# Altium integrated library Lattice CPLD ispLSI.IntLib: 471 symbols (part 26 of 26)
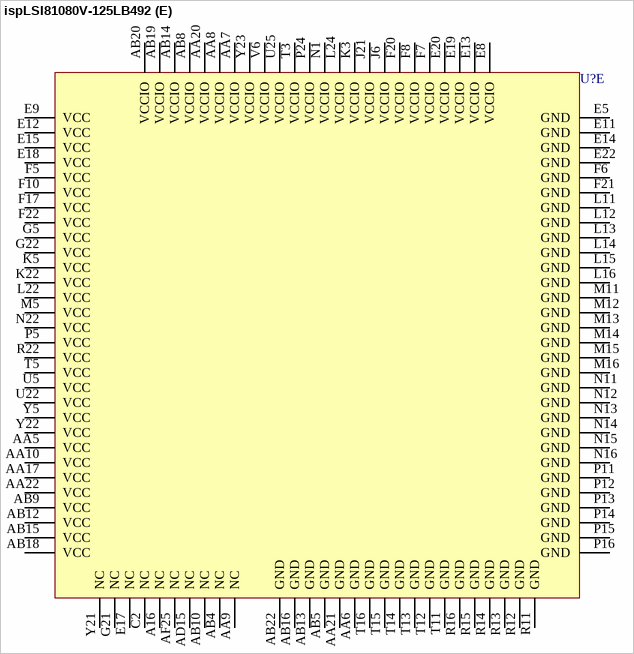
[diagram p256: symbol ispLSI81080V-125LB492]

## ispLSI81080V-125LB492
designator U?
3.3V In-System Programmable SuperBIG High Density PLD
footprint BGA492 (BGA, 492-Leads, Body 35x35mm, Pitch 1.27mm)
3D model 81080V-BGA492 (492-Ball Ball Grid Array (BGA492))
part A pins: A1 I/OB0 <13> (io), A2 TCK (in), A3 I/OB1 <23> (io), A4 I/OB1 <20> (io), A5 I/OB1 <16> (io), A6 I/OB2 <23> (io), A7 I/OB2 <19> (io), A8 I/OB2 <15> (io), A15 QIOCLK2 (in), AB1 I/OB0 <1> (io), AB2 I/OB0 <2> (io), AB3 I/OB0 <3> (io), AB6 I/OB0 <11> (io), AB7 I/OB1 <10> (io), AB17 CLKEN (in), AC1 I/OB0 <4> (io), AC2 I/OB0 <5> (io), AC3 I/OB0 <6> (io), AC4 TMS (in), AC5 I/OB1 <7> (io), AC6 I/OB2 <0> (io), AC7 I/OB2 <4> (io), AC8 I/OB2 <8> (io), AC15 CLK0 (in), AD1 I/OB0 <7> (io), AD2 I/OB0 <8> (io), AD3 I/OB0 <9> (io), AD4 I/OB1 <4> (io), AD5 I/OB1 <8> (io), AD6 I/OB2 <1> (io), AD7 I/OB2 <5> (io), AD8 I/OB2 <9> (io), AE1 I/OB0 <10> (io), AE2 I/OB1 <0> (io), AE3 I/OB1 <2> (io), AE4 I/OB1 <5> (io), AE5 I/OB1 <9> (io), AE6 I/OB2 <2> (io), AE7 I/OB2 <6> (io), AE8 I/OB2 <10> (io), AE14 QIOCLK0 (in), AF1 TDI (in), AF2 I/OB1 <1> (io), AF3 I/OB1 <3> (io), AF4 I/OB1 <6> (io), AF5 I/OB1 <11> (io), AF6 I/OB2 <3> (io), AF7 I/OB2 <7> (io), AF8 I/OB2 <11> (io), AF15 GOE0 (in), B1 I/OB0 <19> (io), B2 I/OB0 <18> (io), B3 TDO (out), B4 I/OB1 <21> (io), B5 I/OB1 <17> (io), B6 I/OB1 <12> (io), B7 I/OB2 <20> (io), B8 I/OB2 <16> (io), B9 I/OB2 <12> (io), B15 CLK2 (in), B26 EPEN (in), C1 I/OB0 <21> (io), C3 I/OB0 <14> (io), C4 I/OB1 <22> (io), C5 I/OB1 <18> (io), C6 I/OB1 <14> (io), C7 I/OB2 <21> (io), C8 I/OB2 <17> (io), C9 I/OB2 <13> (io), D1 I/OB0 <23> (io), D2 I/OB0 <22> (io), D3 I/OB0 <20> (io), D4 I/OB0 <15> (io), D5 I/OB1 <19> (io), D6 I/OB1 <15> (io), D7 I/OB2 <22> (io), D8 I/OB2 <18> (io), D9 I/OB2 <14> (io), D16 GOE2 (in), E6 I/OB0 <12> (io), E7 I/OB1 <13> (io), E16 IOCLKEN (in), F9 I/OB0 <17> (io), G6 I/OB0 <16> (io), L5 TOE (in), N3 QIOCLK3 (in), N5 GOE3 (in), P2 SET/RESET (in), P22 QIOCLK1 (in), P23 GOE1 (in), R24 CLK1 (in), Y6 I/OB0 <0> (io)
part B pins: A9 I/OB3 <23> (io), A10 I/OB3 <19> (io), A11 I/OB3 <15> (io), A12 I/OB3 <12> (io), A13 I/OB4 <20> (io), A14 I/OB4 <15> (io), A17 I/OB5 <21> (io), A18 I/OB5 <17> (io), A19 I/OB5 <13> (io), A20 I/OB6 <20> (io), A21 I/OB6 <16> (io), A22 I/OB6 <12> (io), AA19 I/OB6 <3> (io), AB11 I/OB3 <10> (io), AC9 I/OB3 <0> (io), AC10 I/OB3 <4> (io), AC11 I/OB3 <11> (io), AC12 I/OB4 <4> (io), AC13 I/OB4 <8> (io), AC14 I/OB4 <9> (io), AC16 I/OB5 <2> (io), AC17 I/OB5 <8> (io), AC18 I/OB6 <0> (io), AC19 I/OB6 <5> (io), AC20 I/OB6 <9> (io), AD9 I/OB3 <1> (io), AD10 I/OB3 <5> (io), AD11 I/OB3 <9> (io), AD12 I/OB4 <3> (io), AD13 I/OB4 <7> (io), AD14 I/OB4 <10> (io), AD16 I/OB5 <3> (io), AD17 I/OB5 <7> (io), AD18 I/OB5 <11> (io), AD19 I/OB6 <4> (io), AD20 I/OB6 <8> (io), AE9 I/OB3 <2> (io), AE10 I/OB3 <6> (io), AE11 I/OB3 <8> (io), AE12 I/OB4 <1> (io), AE13 I/OB4 <5> (io), AE15 I/OB5 <0> (io), AE16 I/OB5 <4> (io), AE17 I/OB5 <6> (io), AE18 I/OB5 <10> (io), AE19 I/OB6 <2> (io), AE20 I/OB6 <7> (io), AE21 I/OB6 <11> (io), AF9 I/OB3 <3> (io), AF10 I/OB3 <7> (io), AF11 I/OB4 <0> (io), AF12 I/OB4 <2> (io), AF13 I/OB4 <6> (io), AF14 I/OB4 <11> (io), AF16 I/OB5 <1> (io), AF17 I/OB5 <5> (io), AF18 I/OB5 <9> (io), AF19 I/OB6 <1> (io), AF20 I/OB6 <6> (io), AF21 I/OB6 <10> (io), B10 I/OB3 <20> (io), B11 I/OB3 <18> (io), B12 I/OB3 <14> (io), B13 I/OB4 <21> (io), B14 I/OB4 <14> (io), B16 I/OB5 <22> (io), B17 I/OB5 <20> (io), B18 I/OB5 <16> (io), B19 I/OB5 <12> (io), B20 I/OB6 <19> (io), B21 I/OB6 <15> (io), C10 I/OB3 <21> (io), C11 I/OB3 <17> (io), C12 I/OB4 <23> (io), C13 I/OB4 <19> (io), C14 I/OB4 <16> (io), C15 I/OB4 <12> (io), C16 I/OB5 <23> (io), C17 I/OB5 <19> (io), C18 I/OB5 <15> (io), C19 I/OB6 <23> (io), C20 I/OB6 <18> (io), C21 I/OB6 <14> (io), D10 I/OB3 <22> (io), D11 I/OB3 <16> (io), D12 I/OB4 <22> (io), D13 I/OB4 <18> (io), D14 I/OB4 <17> (io), D15 I/OB4 <13> (io), D17 I/OB5 <18> (io), D18 I/OB5 <14> (io), D19 I/OB6 <22> (io), D20 I/OB6 <17> (io), D21 I/OB6 <13> (io), E10 I/OB3 <13> (io), F19 I/OB6 <21> (io)
part C pins: A23 I/OB7 <20> (io), A24 I/OB7 <17> (io), A25 I/OB7 <15> (io), A26 I/OB7 <12> (io), AA1 I/OG0 <3> (io), AA2 I/OG0 <2> (io), AA3 I/OG0 <1> (io), AA4 I/OG0 <0> (io), AA18 I/OB8 <11> (io), AA23 I/OG0 <20> (io), AA24 I/OG0 <19> (io), AA25 I/OG0 <18> (io), AA26 I/OG0 <17> (io), AB21 I/OB8 <0> (io), AB23 I/OB8 <8> (io), AB24 I/OG0 <23> (io), AB25 I/OG0 <22> (io), AB26 I/OG0 <21> (io), AC21 I/OB7 <1> (io), AC22 I/OB7 <5> (io), AC23 I/OB8 <3> (io), AC24 I/OB8 <6> (io), AC25 I/OB8 <9> (io), AC26 I/OB8 <10> (io), AD21 I/OB7 <0> (io), AD22 I/OB7 <4> (io), AD23 I/OB7 <8> (io), AD24 I/OB7 <11> (io), AD25 I/OB8 <5> (io), AD26 I/OB8 <7> (io), AE22 I/OB7 <3> (io), AE23 I/OB7 <7> (io), AE24 I/OB7 <10> (io), AE25 I/OB8 <2> (io), AE26 I/OB8 <4> (io), AF22 I/OB7 <2> (io), AF23 I/OB7 <6> (io), AF24 I/OB7 <9> (io), AF26 I/OB8 <1> (io), B22 I/OB7 <23> (io), B23 I/OB7 <19> (io), B24 I/OB7 <16> (io), B25 I/OB7 <14> (io), C22 I/OB7 <22> (io), C23 I/OB7 <18> (io), C24 I/OB8 <21> (io), C25 I/OB8 <20> (io), C26 I/OB8 <19> (io), D22 I/OB7 <21> (io), D23 I/OB7 <13> (io), D24 I/OB8 <18> (io), D25 I/OB8 <17> (io), D26 I/OB8 <16> (io), E21 I/OB8 <22> (io), E23 I/OB8 <15> (io), E24 I/OB8 <14> (io), E25 I/OB8 <13> (io), E26 I/OB8 <12> (io), F18 I/OB8 <23> (io), T2 I/OG1 <0> (io), U1 I/OG1 <2> (io), U2 I/OG1 <3> (io), U3 I/OG1 <4> (io), U4 I/OG1 <5> (io), U6 I/OG0 <11> (io), U21 I/OG0 <12> (io), U23 I/OG1 <22> (io), U24 I/OG1 <23> (io), V1 I/OG1 <6> (io), V2 I/OG1 <8> (io), V3 I/OG1 <9> (io), V4 I/OG1 <10> (io), V5 I/OG1 <7> (io), V21 I/OG0 <16> (io), V22 I/OG1 <16> (io), V23 I/OG1 <17> (io), V24 I/OG1 <18> (io), V25 I/OG1 <19> (io), V26 I/OG1 <20> (io), W1 I/OG1 <11> (io), W2 I/OG0 <10> (io), W3 I/OG0 <9> (io), W4 I/OG0 <8> (io), W5 I/OG1 <1> (io), W22 I/OG1 <21> (io), W23 I/OG1 <12> (io), W24 I/OG1 <13> (io), W25 I/OG1 <14> (io), W26 I/OG1 <15> (io), Y1 I/OG0 <7> (io), Y2 I/OG0 <6> (io), Y3 I/OG0 <5> (io), Y4 I/OG0 <4> (io), Y24 I/OG0 <15> (io), Y25 I/OG0 <14> (io), Y26 I/OG0 <13> (io)
part D pins: E1 I/OG5 <3> (io), E2 I/OG5 <2> (io), E3 I/OG5 <1> (io), E4 I/OG5 <0> (io), F1 I/OG5 <7> (io), F2 I/OG5 <6> (io), F3 I/OG5 <5> (io), F4 I/OG5 <4> (io), F23 I/OG5 <23> (io), F24 I/OG5 <22> (io), F25 I/OG5 <21> (io), F26 I/OG5 <20> (io), G1 I/OG5 <11> (io), G2 I/OG5 <10> (io), G3 I/OG5 <9> (io), G4 I/OG5 <8> (io), G23 I/OG5 <19> (io), G24 I/OG5 <18> (io), G25 I/OG5 <17> (io), G26 I/OG5 <16> (io), H1 I/OG4 <6> (io), H2 I/OG4 <8> (io), H3 I/OG4 <9> (io), H4 I/OG4 <10> (io), H5 I/OG4 <1> (io), H6 I/OG3 <3> (io), H21 I/OG3 <20> (io), H22 I/OG4 <21> (io), H23 I/OG5 <15> (io), H24 I/OG5 <14> (io), H25 I/OG5 <13> (io), H26 I/OG4 <12> (io), J1 I/OG4 <2> (io), J2 I/OG4 <3> (io), J3 I/OG4 <4> (io), J4 I/OG4 <5> (io), J5 I/OG4 <7> (io), J22 I/OG4 <16> (io), J23 I/OG4 <13> (io), J24 I/OG4 <14> (io), J25 I/OG4 <15> (io), J26 I/OG4 <17> (io), K1 I/OG3 <1> (io), K2 I/OG3 <0> (io), K4 I/OG4 <0> (io), K6 I/OG4 <11> (io), K21 I/OG5 <12> (io), K23 I/OG4 <18> (io), K24 I/OG4 <19> (io), K25 I/OG4 <20> (io), K26 I/OG4 <22> (io), L1 I/OG3 <6> (io), L2 I/OG3 <2> (io), L3 I/OG3 <4> (io), L4 I/OG3 <5> (io), L23 I/OG3 <23> (io), L25 I/OG4 <23> (io), L26 I/OG3 <22> (io), M1 I/OG3 <8> (io), M2 I/OG3 <7> (io), M3 I/OG3 <9> (io), M4 I/OG3 <10> (io), M22 I/OG3 <16> (io), M23 I/OG3 <17> (io), M24 I/OG3 <18> (io), M25 I/OG3 <21> (io), M26 I/OG3 <19> (io), N2 I/OG3 <11> (io), N4 I/OG2 <11> (io), N23 I/OG3 <12> (io), N24 I/OG3 <13> (io), N25 I/OG3 <15> (io), N26 I/OG3 <14> (io), P1 I/OG2 <8> (io), P3 I/OG2 <9> (io), P4 I/OG2 <10> (io), P25 I/OG2 <13> (io), P26 I/OG2 <12> (io), R1 I/OG2 <4> (io), R2 I/OG2 <3> (io), R3 I/OG2 <5> (io), R4 I/OG2 <6> (io), R5 I/OG2 <7> (io), R23 I/OG2 <14> (io), R25 I/OG2 <17> (io), R26 I/OG2 <16> (io), T1 I/OG2 <1> (io), T4 I/OG2 <0> (io), T22 I/OG2 <15> (io), T23 I/OG2 <19> (io), T24 I/OG2 <21> (io), T25 I/OG2 <22> (io), T26 I/OG2 <18> (io), U26 I/OG2 <23> (io), W6 I/OG2 <2> (io), W21 I/OG2 <20> (io)
part E pins: A16 NC, AA5 VCC (power), AA6 GND (power), AA7 VCCIO (power), AA8 VCCIO (power), AA9 NC, AA10 VCC (power), AA17 VCC (power), AA20 VCCIO (power), AA21 GND (power), AA22 VCC (power), AB4 NC, AB5 GND (power), AB8 VCCIO (power), AB9 VCC (power), AB10 NC, AB12 VCC (power), AB13 GND (power), AB14 VCCIO (power), AB15 VCC (power), AB16 GND (power), AB18 VCC (power), AB19 VCCIO (power), AB20 VCCIO (power), AB22 GND (power), AD15 NC, AF25 NC, C2 NC, E5 GND (power), E8 VCCIO (power), E9 VCC (power), E11 GND (power), E12 VCC (power), E13 VCCIO (power), E14 GND (power), E15 VCC (power), E17 NC, E18 VCC (power), E19 VCCIO (power), E20 VCCIO (power), E22 GND (power), F5 VCC (power), F6 GND (power), F7 VCCIO (power), F8 VCCIO (power), F10 VCC (power), F17 VCC (power), F20 VCCIO (power), F21 GND (power), F22 VCC (power), G5 VCC (power), G21 NC, G22 VCC (power), J6 VCCIO (power), J21 VCCIO (power), K3 VCCIO (power), K5 VCC (power), K22 VCC (power), L11 GND (power), L12 GND (power), L13 GND (power), L14 GND (power), L15 GND (power), L16 GND (power), L22 VCC (power), L24 VCCIO (power), M5 VCC (power), M11 GND (power), M12 GND (power), M13 GND (power), M14 GND (power), M15 GND (power), M16 GND (power), N1 VCCIO (power), N11 GND (power), N12 GND (power), N13 GND (power), N14 GND (power), N15 GND (power), N16 GND (power), N22 VCC (power), P5 VCC (power), P11 GND (power), P12 GND (power), P13 GND (power), P14 GND (power), P15 GND (power), P16 GND (power), P24 VCCIO (power), R11 GND (power), R12 GND (power), R13 GND (power), R14 GND (power), R15 GND (power), R16 GND (power), R22 VCC (power), T3 VCCIO (power), T5 VCC (power), T11 GND (power), T12 GND (power), T13 GND (power), T14 GND (power), T15 GND (power), T16 GND (power), U5 VCC (power), U22 VCC (power), U25 VCCIO (power), V6 VCCIO (power), Y5 VCC (power), Y21 NC, Y22 VCC (power), Y23 VCCIO (power)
